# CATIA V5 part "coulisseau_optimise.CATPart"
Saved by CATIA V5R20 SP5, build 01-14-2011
Part number: coulisseau_optimise
Bounding box of the stored display mesh (mm): x -34.826 to 35.174, y -15 to 15, z -25 to 25
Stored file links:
  K:\Catia\coulisseau_optimise.CATPart
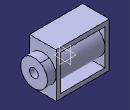
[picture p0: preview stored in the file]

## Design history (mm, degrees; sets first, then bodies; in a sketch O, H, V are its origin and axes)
Body1 (main body)
  Sketch1 on zx-plane, origin (0, 0, 0), H (-1, 0, 0), V (0, 0, 1)
    line L1 (-25.1738, 25) -> (34.8262, 25)
    line L2 (34.8262, 25) -> (34.8262, -25)
    line L3 (34.8262, -25) -> (-25.1738, -25)
    line L4 (-25.1738, -25) -> (-25.1738, 25)
    length L2 = 50
    length L1 = 60
    distance L1 H = 25
    horizontal: L1 H, L3 H
    vertical: L2 V, L4 V
  Pad1: profile Sketch1, direction (0, 1, 0), length 15, mirrored extent
  Sketch2 on zx-plane, origin (0, 0, 0), H (-1, 0, 0), V (0, 0, 1)
    line L1 (-20.1738, 20) -> (29.8262, 20)
    line L2 (29.8262, 20) -> (29.8262, -20)
    line L3 (29.8262, -20) -> (-20.1738, -20)
    line L4 (-20.1738, -20) -> (-20.1738, 20)
    reference projected line E1 (-25.1738, -25) -> (34.8262, -25) from edge [face of Pad1 from Sketch1.L3 | end face of Pad1]
    reference projected line E2 (-25.1738, 25) -> (-25.1738, -25) from edge [face of Pad1 from Sketch1.L4 | end face of Pad1]
    reference projected line E3 (34.8262, 25) -> (-25.1738, 25) from edge [face of Pad1 from Sketch1.L1 | end face of Pad1]
    reference projected line E4 (34.8262, -25) -> (34.8262, 25) from edge [face of Pad1 from Sketch1.L2 | end face of Pad1]
    distance E1 L3 = 5
    distance E2 L4 = 5
    distance L1 E3 = 5
    distance L2 E4 = 5
    horizontal: L1 H, L3 H
    vertical: L2 V, L4 V
  Pocket1: profile Sketch2, direction (0, -1, 0), length 15, mirrored extent
  Sketch3 on zx-plane, origin (0, 0, 0), H (-1, 0, 0), V (0, 0, 1)
    point P1 (-35.1738, 0)
    line L1 (-35.1738, 0) -> (34.8262, 0)
    line L2 (34.8262, 0) -> (34.8262, 15)
    line L3 (34.8262, 15) -> (-35.1738, 15)
    line L4 (-35.1738, 15) -> (-35.1738, 0)
    reference projected line E1 (34.8262, -25) -> (34.8262, 25) from edge [face of Pad1 from Sketch1.L2 | end face of Pad1]
    length L2 = 15
    length L3 = 70
    coincidence: P1 H, L2 E1
    horizontal: L1 H, L3 H
    vertical: L2 V, L4 V
  Shaft1: profile Sketch3, axis Sketch3.L1, angle 360
  Sketch4 on face of Shaft1 from Sketch3.L4, origin (35.1738, 0, 0), H (0, 1, 0), V (0, 0, 1)
    point P1 (0, 0)
    reference projected circle E1 centre (0, 0) radius 15 from edge [face of Shaft1 from Sketch3.L4 | face of Shaft1 from Sketch3.L3]
    concentricity: P1 E1
  Hole1: placed by Sketch4, at (35.1738, 0, 0) direction (-1, 0, 0), diameter 10, through (limit type 3)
